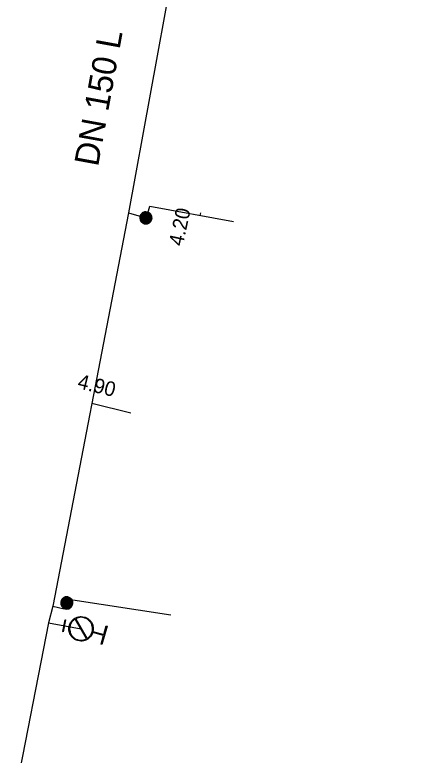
# Model space of a CAD drawing. Extents: x -820257 to -819974, y -1070894 to -1070484.
# Drawn here: x -820131.5 to -820098, y -1070861 to -1070800.1 of the extents above; entities that cross this region are included whole.
import ezdxf

# ---------------------------------------------------------------- set-up
doc = ezdxf.new("R2010")
doc.units = 0
for name, color, linetype in [('Hyd-odbočka', 7, 'Continuous'), ('Hyd-šoupě', 7, 'Continuous'), ('Hydrant', 7, 'Continuous'), ('Oměrka vodovodu', 7, 'Continuous'), ('Oměrka-text', 7, 'Continuous'), ('Přípojka vodovodu', 7, 'Continuous'), ('Přípojkový uzávěr', 7, 'Continuous'), ('Roz-řad', 7, 'Continuous'), ('Roz-řad-popis základní', 7, 'Continuous')]:
    doc.layers.add(name, color=color, linetype=linetype)

msp = doc.modelspace()

# ---------------------------------------------------------------- linework, layer by layer
at = {"layer": 'Hyd-odbočka'}
msp.add_line((-820128.743, -1070850.133), (-820126.06, -1070850.621), dxfattribs=at)
at = {"layer": 'Hyd-šoupě'}
msp.add_lwpolyline([(-820127.352, -1070849.878), (-820127.531, -1070850.862), (-820127.562, -1070850.856), (-820127.383, -1070849.872), (-820127.352, -1070849.878)], dxfattribs=at)
at = {"layer": 'Hydrant'}
for points in [[(-820125.621, -1070851.452), (-820126.553, -1070849.82)], [(-820126.498, -1070849.79), (-820125.569, -1070851.422)], [(-820125.087, -1070850.856), (-820124.183, -1070851.104), (-820123.985, -1070850.38), (-820123.924, -1070850.397), (-820124.338, -1070851.904), (-820124.398, -1070851.887), (-820124.2, -1070851.164), (-820125.104, -1070850.916)]]:
    msp.add_lwpolyline(points, dxfattribs=at)
for points in [[(-820125.104, -1070850.916), (-820125.174, -1070851.142), (-820125.35, -1070851.326), (-820125.537, -1070851.522), (-820125.805, -1070851.589), (-820126.072, -1070851.655), (-820126.324, -1070851.586), (-820126.575, -1070851.517), (-820126.77, -1070851.327), (-820126.965, -1070851.137), (-820127.029, -1070850.872), (-820127.093, -1070850.608), (-820127.024, -1070850.357), (-820126.956, -1070850.106), (-820126.765, -1070849.912), (-820126.575, -1070849.717), (-820126.311, -1070849.652), (-820126.046, -1070849.588), (-820125.795, -1070849.657), (-820125.543, -1070849.726), (-820125.347, -1070849.92), (-820125.151, -1070850.113), (-820125.09, -1070850.377), (-820125.032, -1070850.624), (-820125.087, -1070850.856)], [(-820126.553, -1070849.82), (-820126.643, -1070849.876), (-820126.72, -1070849.956), (-820126.899, -1070850.138), (-820126.964, -1070850.374), (-820127.029, -1070850.609), (-820126.968, -1070850.857), (-820126.908, -1070851.106), (-820126.725, -1070851.283), (-820126.543, -1070851.461), (-820126.308, -1070851.526), (-820126.07, -1070851.591), (-820125.82, -1070851.528), (-820125.713, -1070851.5), (-820125.621, -1070851.452)], [(-820125.569, -1070851.422), (-820125.473, -1070851.363), (-820125.394, -1070851.282), (-820125.218, -1070851.097), (-820125.156, -1070850.869), (-820125.093, -1070850.641), (-820125.151, -1070850.393), (-820125.208, -1070850.144), (-820125.391, -1070849.963), (-820125.575, -1070849.782), (-820125.812, -1070849.717), (-820126.047, -1070849.653), (-820126.295, -1070849.714), (-820126.403, -1070849.739), (-820126.498, -1070849.79)]]:
    msp.add_open_spline(points, degree=3, dxfattribs=at)
at = {"layer": 'Oměrka vodovodu'}
for p, q in [((-820116.243, -1070816.594), (-820116.198, -1070816.384)), ((-820125.182, -1070832.054), (-820121.953, -1070832.843))]:
    msp.add_line(p, q, dxfattribs=at)
at = {"layer": 'Přípojka vodovodu'}
for points in [[(-820122.165, -1070816.376), (-820120.722, -1070816.786), (-820120.683, -1070816.797), (-820120.409, -1070815.826), (-820113.513, -1070817.097)], [(-820128.396, -1070848.754), (-820127.451, -1070848.976), (-820127.237, -1070848.492), (-820127.1, -1070848.183), (-820118.673, -1070849.466)]]:
    msp.add_lwpolyline(points, dxfattribs=at)
at = {"layer": 'Přípojkový uzávěr'}
for points in [[(-820120.585, -1070816.305), (-820120.464, -1070816.339), (-820120.367, -1070816.434), (-820120.269, -1070816.528), (-820120.237, -1070816.663), (-820120.205, -1070816.797), (-820120.241, -1070816.923), (-820120.276, -1070817.048), (-820120.372, -1070817.144), (-820120.468, -1070817.24), (-820120.6, -1070817.271), (-820120.733, -1070817.302), (-820120.859, -1070817.266), (-820120.983, -1070817.231), (-820121.08, -1070817.135), (-820121.176, -1070817.039), (-820121.207, -1070816.907), (-820121.238, -1070816.774), (-820121.203, -1070816.65), (-820121.167, -1070816.524), (-820121.069, -1070816.426), (-820120.972, -1070816.329), (-820120.839, -1070816.299), (-820120.707, -1070816.27), (-820120.585, -1070816.305)], [(-820120.598, -1070816.35), (-820120.708, -1070816.318), (-820120.828, -1070816.345), (-820120.948, -1070816.371), (-820121.037, -1070816.46), (-820121.125, -1070816.548), (-820121.157, -1070816.662), (-820121.19, -1070816.776), (-820121.162, -1070816.895), (-820121.134, -1070817.015), (-820121.046, -1070817.102), (-820120.958, -1070817.189), (-820120.846, -1070817.221), (-820120.732, -1070817.254), (-820120.612, -1070817.226), (-820120.491, -1070817.198), (-820120.405, -1070817.11), (-820120.318, -1070817.023), (-820120.286, -1070816.91), (-820120.253, -1070816.796), (-820120.283, -1070816.674), (-820120.312, -1070816.552), (-820120.4, -1070816.467), (-820120.488, -1070816.381), (-820120.598, -1070816.35)], [(-820120.607, -1070816.383), (-820120.505, -1070816.411), (-820120.424, -1070816.491), (-820120.343, -1070816.57), (-820120.316, -1070816.682), (-820120.289, -1070816.795), (-820120.319, -1070816.901), (-820120.348, -1070817.005), (-820120.428, -1070817.086), (-820120.508, -1070817.167), (-820120.62, -1070817.193), (-820120.731, -1070817.218), (-820120.836, -1070817.189), (-820120.941, -1070817.159), (-820121.022, -1070817.078), (-820121.103, -1070816.998), (-820121.129, -1070816.887), (-820121.154, -1070816.776), (-820121.125, -1070816.672), (-820121.095, -1070816.566), (-820121.013, -1070816.484), (-820120.931, -1070816.403), (-820120.82, -1070816.378), (-820120.709, -1070816.354), (-820120.607, -1070816.383)], [(-820120.62, -1070816.425), (-820120.77, -1070816.382), (-820120.905, -1070816.458), (-820121.04, -1070816.534), (-820121.082, -1070816.684), (-820121.125, -1070816.833), (-820121.049, -1070816.968), (-820120.973, -1070817.104), (-820120.825, -1070817.146), (-820120.675, -1070817.189), (-820120.539, -1070817.113), (-820120.403, -1070817.038), (-820120.361, -1070816.889), (-820120.318, -1070816.739), (-820120.393, -1070816.603), (-820120.468, -1070816.468), (-820120.62, -1070816.425)], [(-820120.632, -1070816.469), (-820120.5, -1070816.506), (-820120.435, -1070816.625), (-820120.369, -1070816.743), (-820120.406, -1070816.874), (-820120.444, -1070817.005), (-820120.562, -1070817.071), (-820120.681, -1070817.137), (-820120.812, -1070817.1), (-820120.943, -1070817.063), (-820121.009, -1070816.944), (-820121.075, -1070816.826), (-820121.038, -1070816.695), (-820121, -1070816.564), (-820120.882, -1070816.498), (-820120.764, -1070816.431), (-820120.632, -1070816.469)], [(-820120.643, -1070816.507), (-820120.759, -1070816.474), (-820120.863, -1070816.532), (-820120.967, -1070816.591), (-820121, -1070816.706), (-820121.032, -1070816.821), (-820120.974, -1070816.925), (-820120.916, -1070817.029), (-820120.801, -1070817.062), (-820120.686, -1070817.095), (-820120.582, -1070817.037), (-820120.477, -1070816.978), (-820120.444, -1070816.863), (-820120.412, -1070816.748), (-820120.469, -1070816.644), (-820120.527, -1070816.54), (-820120.643, -1070816.507)], [(-820120.654, -1070816.545), (-820120.553, -1070816.574), (-820120.503, -1070816.664), (-820120.453, -1070816.754), (-820120.481, -1070816.854), (-820120.509, -1070816.954), (-820120.6, -1070817.004), (-820120.69, -1070817.054), (-820120.79, -1070817.026), (-820120.889, -1070816.998), (-820120.94, -1070816.908), (-820120.99, -1070816.817), (-820120.962, -1070816.718), (-820120.934, -1070816.618), (-820120.844, -1070816.567), (-820120.754, -1070816.516), (-820120.654, -1070816.545)], [(-820120.666, -1070816.59), (-820120.747, -1070816.567), (-820120.821, -1070816.607), (-820120.894, -1070816.648), (-820120.917, -1070816.73), (-820120.94, -1070816.811), (-820120.899, -1070816.884), (-820120.859, -1070816.957), (-820120.777, -1070816.98), (-820120.696, -1070817.003), (-820120.623, -1070816.963), (-820120.549, -1070816.922), (-820120.526, -1070816.841), (-820120.503, -1070816.759), (-820120.544, -1070816.686), (-820120.585, -1070816.613), (-820120.666, -1070816.59)], [(-820120.676, -1070816.623), (-820120.608, -1070816.642), (-820120.574, -1070816.703), (-820120.54, -1070816.763), (-820120.56, -1070816.831), (-820120.579, -1070816.899), (-820120.64, -1070816.932), (-820120.701, -1070816.966), (-820120.768, -1070816.947), (-820120.835, -1070816.928), (-820120.869, -1070816.867), (-820120.903, -1070816.807), (-820120.884, -1070816.739), (-820120.865, -1070816.671), (-820120.804, -1070816.638), (-820120.743, -1070816.604), (-820120.676, -1070816.623)], [(-820120.688, -1070816.665), (-820120.738, -1070816.651), (-820120.783, -1070816.676), (-820120.827, -1070816.702), (-820120.842, -1070816.752), (-820120.856, -1070816.801), (-820120.831, -1070816.847), (-820120.805, -1070816.892), (-820120.756, -1070816.906), (-820120.706, -1070816.92), (-820120.661, -1070816.895), (-820120.615, -1070816.87), (-820120.601, -1070816.82), (-820120.587, -1070816.77), (-820120.612, -1070816.725), (-820120.637, -1070816.68), (-820120.688, -1070816.665)], [(-820120.701, -1070816.71), (-820120.669, -1070816.719), (-820120.653, -1070816.747), (-820120.638, -1070816.775), (-820120.647, -1070816.807), (-820120.656, -1070816.838), (-820120.683, -1070816.854), (-820120.711, -1070816.87), (-820120.743, -1070816.861), (-820120.774, -1070816.852), (-820120.79, -1070816.824), (-820120.806, -1070816.795), (-820120.797, -1070816.764), (-820120.788, -1070816.732), (-820120.76, -1070816.717), (-820120.732, -1070816.702), (-820120.701, -1070816.71)], [(-820120.709, -1070816.74), (-820120.728, -1070816.735), (-820120.745, -1070816.744), (-820120.761, -1070816.753), (-820120.767, -1070816.773), (-820120.772, -1070816.792), (-820120.763, -1070816.808), (-820120.753, -1070816.825), (-820120.735, -1070816.831), (-820120.715, -1070816.836), (-820120.699, -1070816.827), (-820120.682, -1070816.817), (-820120.677, -1070816.798), (-820120.671, -1070816.779), (-820120.681, -1070816.762), (-820120.69, -1070816.746), (-820120.709, -1070816.74)], [(-820127.694, -1070848.289), (-820127.643, -1070848.174), (-820127.536, -1070848.091), (-820127.429, -1070848.008), (-820127.291, -1070847.995), (-820127.154, -1070847.981), (-820127.034, -1070848.034), (-820126.915, -1070848.087), (-820126.833, -1070848.195), (-820126.751, -1070848.304), (-820126.739, -1070848.439), (-820126.727, -1070848.575), (-820126.78, -1070848.694), (-820126.832, -1070848.813), (-820126.941, -1070848.895), (-820127.049, -1070848.977), (-820127.185, -1070848.989), (-820127.32, -1070849.001), (-820127.439, -1070848.949), (-820127.558, -1070848.896), (-820127.641, -1070848.786), (-820127.724, -1070848.676), (-820127.735, -1070848.54), (-820127.745, -1070848.405), (-820127.694, -1070848.289)], [(-820127.651, -1070848.308), (-820127.698, -1070848.413), (-820127.688, -1070848.536), (-820127.679, -1070848.658), (-820127.603, -1070848.758), (-820127.528, -1070848.858), (-820127.42, -1070848.906), (-820127.312, -1070848.954), (-820127.19, -1070848.943), (-820127.067, -1070848.932), (-820126.969, -1070848.857), (-820126.87, -1070848.782), (-820126.823, -1070848.675), (-820126.775, -1070848.567), (-820126.786, -1070848.444), (-820126.797, -1070848.321), (-820126.871, -1070848.223), (-820126.945, -1070848.125), (-820127.053, -1070848.077), (-820127.161, -1070848.029), (-820127.286, -1070848.041), (-820127.411, -1070848.053), (-820127.508, -1070848.129), (-820127.605, -1070848.204), (-820127.651, -1070848.308)], [(-820127.62, -1070848.322), (-820127.577, -1070848.225), (-820127.487, -1070848.156), (-820127.398, -1070848.086), (-820127.283, -1070848.075), (-820127.167, -1070848.064), (-820127.067, -1070848.109), (-820126.967, -1070848.153), (-820126.898, -1070848.243), (-820126.83, -1070848.334), (-820126.82, -1070848.448), (-820126.81, -1070848.561), (-820126.854, -1070848.661), (-820126.898, -1070848.761), (-820126.989, -1070848.83), (-820127.08, -1070848.899), (-820127.193, -1070848.909), (-820127.306, -1070848.919), (-820127.406, -1070848.875), (-820127.506, -1070848.83), (-820127.576, -1070848.738), (-820127.645, -1070848.646), (-820127.654, -1070848.532), (-820127.663, -1070848.419), (-820127.62, -1070848.322)], [(-820127.58, -1070848.341), (-820127.643, -1070848.483), (-820127.587, -1070848.627), (-820127.531, -1070848.771), (-820127.388, -1070848.835), (-820127.246, -1070848.897), (-820127.101, -1070848.841), (-820126.957, -1070848.785), (-820126.894, -1070848.644), (-820126.831, -1070848.501), (-820126.887, -1070848.356), (-820126.943, -1070848.212), (-820127.085, -1070848.149), (-820127.227, -1070848.086), (-820127.372, -1070848.141), (-820127.516, -1070848.196), (-820127.58, -1070848.341)], [(-820127.538, -1070848.359), (-820127.483, -1070848.234), (-820127.356, -1070848.185), (-820127.23, -1070848.137), (-820127.105, -1070848.192), (-820126.981, -1070848.247), (-820126.932, -1070848.374), (-820126.883, -1070848.5), (-820126.938, -1070848.625), (-820126.993, -1070848.75), (-820127.12, -1070848.798), (-820127.246, -1070848.847), (-820127.371, -1070848.792), (-820127.496, -1070848.737), (-820127.545, -1070848.61), (-820127.594, -1070848.484), (-820127.538, -1070848.359)], [(-820127.502, -1070848.375), (-820127.551, -1070848.485), (-820127.507, -1070848.596), (-820127.464, -1070848.707), (-820127.355, -1070848.756), (-820127.246, -1070848.804), (-820127.134, -1070848.761), (-820127.023, -1070848.719), (-820126.974, -1070848.609), (-820126.926, -1070848.499), (-820126.969, -1070848.388), (-820127.012, -1070848.276), (-820127.121, -1070848.228), (-820127.231, -1070848.18), (-820127.342, -1070848.222), (-820127.453, -1070848.265), (-820127.502, -1070848.375)], [(-820127.466, -1070848.391), (-820127.423, -1070848.295), (-820127.327, -1070848.258), (-820127.23, -1070848.221), (-820127.135, -1070848.263), (-820127.041, -1070848.305), (-820127.003, -1070848.401), (-820126.966, -1070848.498), (-820127.008, -1070848.593), (-820127.05, -1070848.687), (-820127.147, -1070848.725), (-820127.243, -1070848.762), (-820127.338, -1070848.72), (-820127.433, -1070848.678), (-820127.47, -1070848.582), (-820127.508, -1070848.486), (-820127.466, -1070848.391)], [(-820127.423, -1070848.409), (-820127.457, -1070848.487), (-820127.427, -1070848.565), (-820127.397, -1070848.643), (-820127.32, -1070848.677), (-820127.242, -1070848.712), (-820127.164, -1070848.681), (-820127.086, -1070848.651), (-820127.052, -1070848.574), (-820127.018, -1070848.497), (-820127.048, -1070848.419), (-820127.078, -1070848.34), (-820127.155, -1070848.306), (-820127.233, -1070848.272), (-820127.311, -1070848.302), (-820127.389, -1070848.332), (-820127.423, -1070848.409)], [(-820127.392, -1070848.423), (-820127.363, -1070848.359), (-820127.298, -1070848.334), (-820127.234, -1070848.309), (-820127.169, -1070848.338), (-820127.105, -1070848.366), (-820127.08, -1070848.431), (-820127.055, -1070848.496), (-820127.083, -1070848.56), (-820127.112, -1070848.624), (-820127.177, -1070848.649), (-820127.241, -1070848.674), (-820127.306, -1070848.646), (-820127.37, -1070848.617), (-820127.395, -1070848.553), (-820127.42, -1070848.488), (-820127.392, -1070848.423)], [(-820127.351, -1070848.441), (-820127.372, -1070848.489), (-820127.354, -1070848.537), (-820127.335, -1070848.585), (-820127.287, -1070848.606), (-820127.24, -1070848.627), (-820127.192, -1070848.608), (-820127.143, -1070848.589), (-820127.123, -1070848.542), (-820127.102, -1070848.495), (-820127.12, -1070848.446), (-820127.139, -1070848.398), (-820127.186, -1070848.377), (-820127.234, -1070848.356), (-820127.282, -1070848.375), (-820127.33, -1070848.393), (-820127.351, -1070848.441)], [(-820127.308, -1070848.46), (-820127.295, -1070848.43), (-820127.265, -1070848.418), (-820127.236, -1070848.407), (-820127.205, -1070848.42), (-820127.176, -1070848.433), (-820127.164, -1070848.463), (-820127.152, -1070848.493), (-820127.166, -1070848.523), (-820127.179, -1070848.553), (-820127.209, -1070848.565), (-820127.239, -1070848.576), (-820127.269, -1070848.563), (-820127.299, -1070848.55), (-820127.31, -1070848.52), (-820127.322, -1070848.49), (-820127.308, -1070848.46)], [(-820127.28, -1070848.473), (-820127.288, -1070848.491), (-820127.281, -1070848.509), (-820127.274, -1070848.527), (-820127.256, -1070848.535), (-820127.238, -1070848.543), (-820127.22, -1070848.536), (-820127.202, -1070848.529), (-820127.194, -1070848.511), (-820127.186, -1070848.493), (-820127.193, -1070848.475), (-820127.2, -1070848.457), (-820127.218, -1070848.449), (-820127.236, -1070848.441), (-820127.254, -1070848.448), (-820127.272, -1070848.455), (-820127.28, -1070848.473)]]:
    msp.add_open_spline(points, degree=3, dxfattribs=at)
at = {"layer": 'Roz-řad'}
for points in [[(-820104.571, -1070768.915), (-820110.577, -1070780.742), (-820118.59, -1070796.818), (-820122.165, -1070816.376), (-820128.396, -1070848.754), (-820128.743, -1070850.133)], [(-820128.743, -1070850.133), (-820131.517, -1070864.357), (-820131.167, -1070866.699), (-820098.993, -1070888.291), (-820097.968, -1070888.921)]]:
    msp.add_lwpolyline(points, dxfattribs=at)

# ---------------------------------------------------------------- texts
at = {"layer": 'Oměrka-text'}
for s, rotation, p in [(' 4.20', 77.90524, (-820117.78, -1070819.606)), (' 4.90', 346.26893, (-820126.85, -1070830.69))]:
    msp.add_text(s, height=1.2, rotation=rotation, dxfattribs=at).set_placement(p)
at = {"layer": 'Roz-řad-popis základní'}
msp.add_text('DN 150 L', height=2, rotation=79.64131, dxfattribs=at).set_placement((-820124.663, -1070812.624))

doc.saveas('drawing.dxf')
